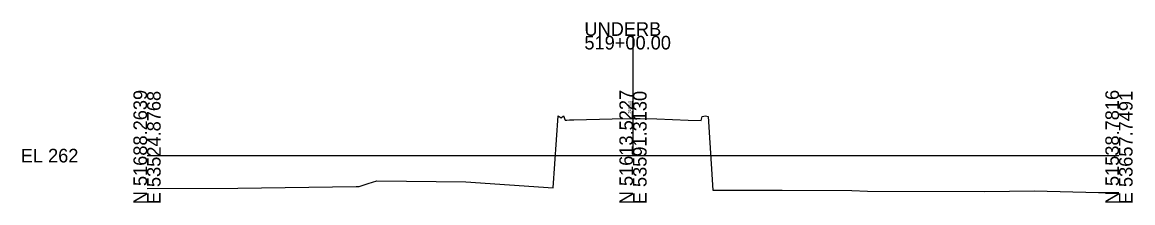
# Model space of a CAD drawing. Extents: x 12366 to 12594, y 96215 to 101752.
# Drawn here: x 12365.6 to 12594.1, y 97714.9 to 97752.1 of the extents above; entities that cross this region are included whole.
import ezdxf

# ---------------------------------------------------------------- set-up
doc = ezdxf.new("R2010")
doc.units = 0
for name, color, linetype in [('Level 10', 7, 'Continuous'), ('Level 60', 7, 'Continuous'), ('Level 63', 7, 'Continuous')]:
    doc.layers.add(name, color=color, linetype=linetype)

msp = doc.modelspace()

# ---------------------------------------------------------------- linework, layer by layer
at = {"layer": 'Level 60'}
for p, q in [((12474.88, 97717.99), (12475.87, 97732.81)), ((12475.87, 97732.81), (12476.54, 97732.43)), ((12476.54, 97732.43), (12477.02, 97732.85)), ((12477.02, 97732.85), (12477.36, 97731.94)), ((12477.36, 97731.94), (12477.67, 97731.97)), ((12477.67, 97731.97), (12478.2, 97731.99)), ((12478.2, 97731.99), (12479.09, 97732.03)), ((12479.09, 97732.03), (12487.04, 97732.2)), ((12487.04, 97732.2), (12491.34, 97732.28)), ((12491.34, 97732.28), (12492.77, 97732.26)), ((12492.77, 97732.26), (12496.21, 97732.18)), ((12496.21, 97732.18), (12502.66, 97731.93)), ((12502.66, 97731.93), (12505.32, 97731.85)), ((12505.32, 97731.85), (12505.55, 97732.68)), ((12505.55, 97732.68), (12506.22, 97732.8)), ((12506.22, 97732.8), (12506.79, 97732.66)), ((12506.79, 97732.66), (12507.76, 97717.57)), ((12391.3, 97717.88), (12409.98, 97717.92)), ((12409.98, 97717.92), (12434.33, 97718.31)), ((12434.33, 97718.31), (12434.93, 97718.32)), ((12434.93, 97718.32), (12436.83, 97718.93)), ((12436.83, 97718.93), (12438.6, 97719.49)), ((12438.6, 97719.49), (12456.87, 97719.22)), ((12456.87, 97719.22), (12474.88, 97717.99)), ((12507.76, 97717.57), (12508.36, 97717.57)), ((12508.36, 97717.57), (12521.98, 97717.57)), ((12521.98, 97717.57), (12536.3, 97717.47)), ((12536.3, 97717.47), (12539.54, 97717.36)), ((12539.54, 97717.36), (12563.61, 97717.25)), ((12563.61, 97717.25), (12573.93, 97717.37)), ((12573.93, 97717.37), (12587.06, 97717.08)), ((12587.06, 97717.08), (12591.3, 97717.03))]:
    msp.add_line(p, q, dxfattribs=at)
at = {"layer": 'Level 63'}
for p, q in [((12491.3, 97724.64), (12491.3, 97749.28)), ((12391.3, 97724.64), (12491.3, 97724.64)), ((12491.3, 97724.64), (12591.3, 97724.64))]:
    msp.add_line(p, q, dxfattribs=at)

# ---------------------------------------------------------------- texts
at = {"layer": 'Level 10'}
msp.add_text('269.64', height=0.6, rotation=90, dxfattribs=at).set_placement((12490.9, 97733.28))
at = {"layer": 'Level 63'}
for s, p in [('UNDERB', (12481.3, 97749.28)), ('519+00.00', (12481.3, 97746.48)), ('EL 262', (12365.31, 97723.24))]:
    msp.add_text(s, height=2.8, dxfattribs=at).set_placement(p)
for s, p in [('N 51688.2639', (12391.3, 97714.64)), ('E 53524.8768', (12394.1, 97714.64)), ('N 51613.5227', (12491.3, 97714.64)), ('E 53591.3130', (12494.1, 97714.64)), ('N 51538.7816', (12591.3, 97714.64)), ('E 53657.7491', (12594.1, 97714.64))]:
    msp.add_text(s, height=2.8, rotation=90, dxfattribs=at).set_placement(p)

doc.saveas('drawing.dxf')
